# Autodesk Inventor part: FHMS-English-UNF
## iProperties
Author: cdotson
Shininess: 60.0
PropertySet Name: _Private Model Information
Created: 2001-02
Part Number: FHMS-English-UNF
Material: Steel, High Strength Low Alloy
Document SubType Name: Modeling
Designer: cdotson
Control State: 0
Master: False
Checked Out: False
PropertySet Name: Design Tracking Control
Density: 7.84
Volumn: 0.9570212615531521
Area: 7.706801682804725
PropertySet Name: Model Information
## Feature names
1. Extrusion1
2. Extrusion2
3. Extrusion3
4. Chamfer2
5. Fillet1
